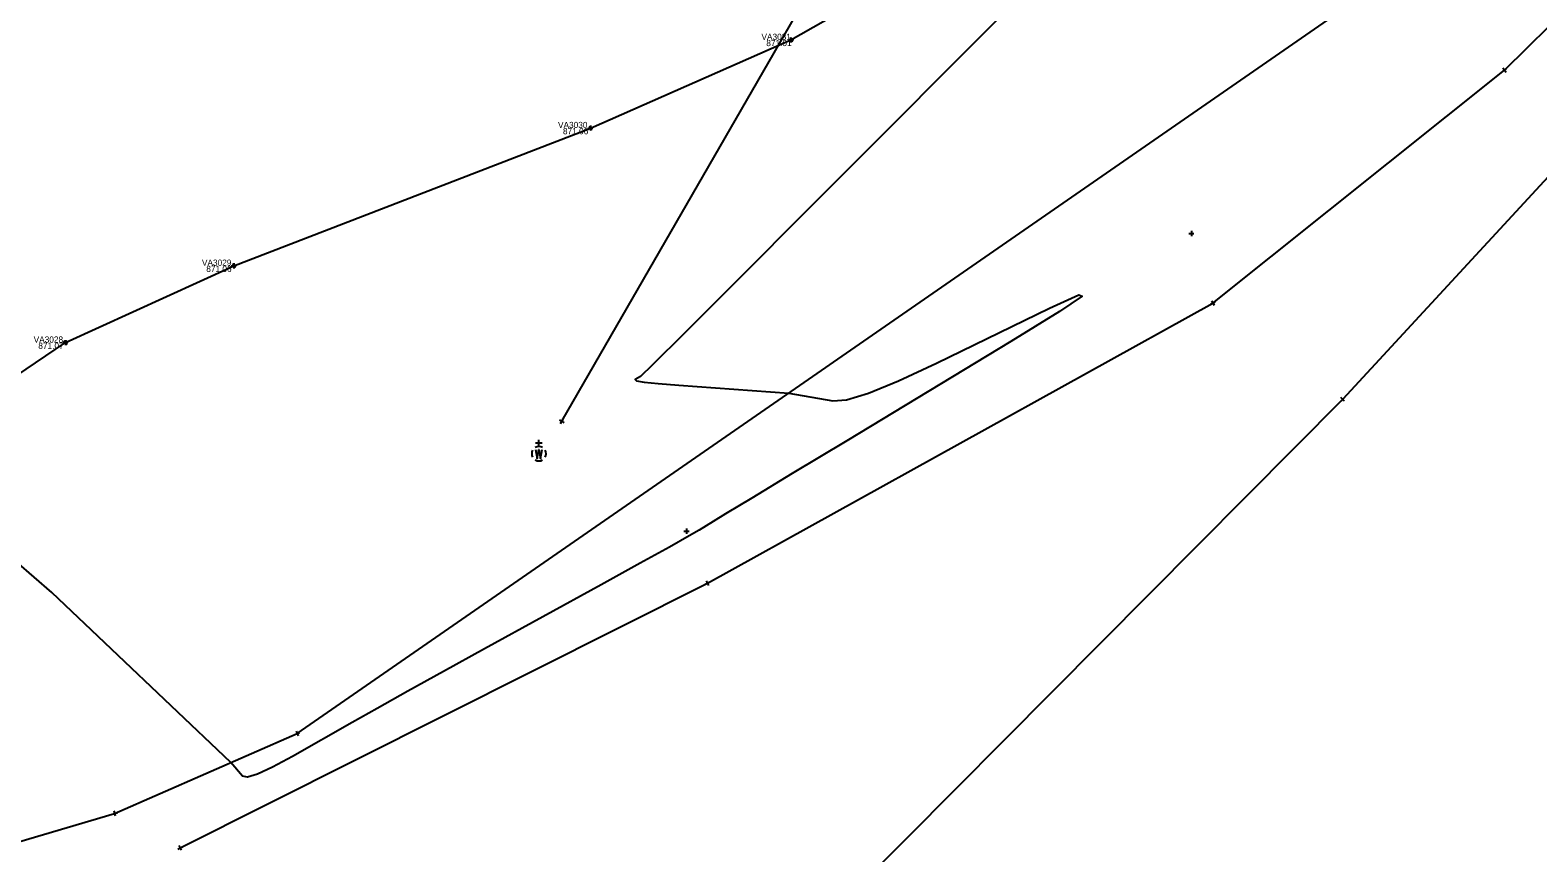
# Model space of a CAD drawing. Extents: x 1475580 to 1482245, y 377938 to 382467.
# Drawn here: x 1481280.89 to 1481295.51, y 378080.79 to 378088.76 of the extents above; entities that cross this region are included whole.
import ezdxf

# ---------------------------------------------------------------- set-up
doc = ezdxf.new("R2010")
doc.units = 0
for name, color, linetype in [('DT_X_Contour_Minor', 7, 'Continuous'), ('PV_X_Curb', 7, 'Continuous'), ('PV_X_EOP', 7, 'Continuous'), ('PV_X_Walk', 7, 'Continuous'), ('SV_X_Shot_Marker', 7, 'Continuous'), ('SV_X_Text_Elevation', 7, 'Continuous'), ('SV_X_Text_Name', 7, 'Continuous'), ('UT_X_Water', 7, 'Continuous'), ('UT_X_Water_Cells', 7, 'Continuous')]:
    doc.layers.add(name, color=color, linetype=linetype)

msp = doc.modelspace()

# ---------------------------------------------------------------- linework, layer by layer
at = {"layer": 'DT_X_Contour_Minor'}
msp.add_lwpolyline([(1481290.585, 378089.188), (1481288.447, 378087.042), (1481287.744, 378086.336), (1481287.236, 378085.829), (1481286.924, 378085.52), (1481286.808, 378085.409), (1481286.759, 378085.379), (1481286.771, 378085.368), (1481286.846, 378085.354), (1481286.982, 378085.34), (1481287.18, 378085.324), (1481288.248, 378085.248), (1481288.675, 378085.173), (1481288.807, 378085.184), (1481289.018, 378085.249), (1481289.309, 378085.367), (1481289.679, 378085.539), (1481290.773, 378086.07), (1481291.058, 378086.199), (1481291.09, 378086.189), (1481290.871, 378086.038), (1481290.4, 378085.748), (1481288.809, 378084.787), (1481288.281, 378084.468), (1481287.888, 378084.231), (1481287.633, 378084.077), (1481287.514, 378084.004), (1481287.378, 378083.921), (1481287.281, 378083.864), (1481287.09, 378083.757), (1481286.806, 378083.6), (1481286.429, 378083.392), (1481285.298, 378082.77), (1481284.899, 378082.551), (1481284.553, 378082.359), (1481284.258, 378082.194), (1481284.015, 378082.057), (1481283.437, 378081.728), (1481283.244, 378081.623), (1481283.099, 378081.557), (1481283.002, 378081.528), (1481282.953, 378081.537), (1481282.838, 378081.668), (1481281.105, 378083.318), (1481280.762, 378083.614)], dxfattribs=at)
msp.add_lwpolyline([(1481290.585, 378089.188), (1481288.447, 378087.042), (1481287.744, 378086.336), (1481287.236, 378085.829), (1481286.924, 378085.52), (1481286.808, 378085.409), (1481286.759, 378085.379), (1481286.771, 378085.368), (1481286.846, 378085.354), (1481286.982, 378085.34), (1481287.18, 378085.324), (1481288.248, 378085.248), (1481288.675, 378085.173), (1481288.807, 378085.184), (1481289.018, 378085.249), (1481289.309, 378085.367), (1481289.679, 378085.539), (1481290.773, 378086.07), (1481291.058, 378086.199), (1481291.09, 378086.189), (1481290.871, 378086.038), (1481290.4, 378085.748), (1481288.809, 378084.787), (1481288.281, 378084.468), (1481287.888, 378084.231), (1481287.633, 378084.077), (1481287.514, 378084.004), (1481287.378, 378083.921), (1481287.281, 378083.864), (1481287.09, 378083.757), (1481286.806, 378083.6), (1481286.429, 378083.392), (1481285.298, 378082.77), (1481284.899, 378082.551), (1481284.553, 378082.359), (1481284.258, 378082.194), (1481284.015, 378082.057), (1481283.437, 378081.728), (1481283.244, 378081.623), (1481283.099, 378081.557), (1481283.002, 378081.528), (1481282.953, 378081.537), (1481282.838, 378081.668), (1481281.105, 378083.318), (1481280.762, 378083.614)], dxfattribs=at)
at = {"layer": 'PV_X_Curb'}
for points in [[(1481260.817, 378083.891), (1481263.757, 378082.165), (1481266.786, 378080.843), (1481269.995, 378079.971), (1481273.12, 378079.589), (1481275.926, 378079.677), (1481277.731, 378080.003), (1481281.712, 378081.176), (1481283.483, 378081.95), (1481295.923, 378090.562), (1481299.451, 378094.31), (1481300.913, 378095.81), (1481302.083, 378097.025), (1481320.414, 378116.343), (1481340.859, 378137.833), (1481361.576, 378159.638), (1481382.233, 378181.406), (1481396.451, 378196.415), (1481396.638, 378196.668), (1481396.634, 378196.695)], [(1481282.347, 378080.842), (1481287.458, 378083.408), (1481292.356, 378086.121), (1481295.185, 378088.378), (1481296.787, 378089.957), (1481300.004, 378093.511), (1481302.707, 378096.342), (1481321.206, 378115.602), (1481341.53, 378137.195), (1481362.313, 378159.083), (1481382.833, 378180.775), (1481397.357, 378195.764)], [(1481282.347, 378080.842), (1481287.458, 378083.408), (1481292.356, 378086.121), (1481295.185, 378088.378), (1481296.787, 378089.957), (1481300.004, 378093.511), (1481302.707, 378096.342), (1481321.206, 378115.602), (1481341.53, 378137.195), (1481362.313, 378159.083), (1481382.833, 378180.775), (1481397.357, 378195.764)]]:
    msp.add_lwpolyline(points, dxfattribs=at)
at = {"layer": 'PV_X_EOP'}
msp.add_lwpolyline([(1481397.134, 378196.295), (1481398.125, 378195.357), (1481383.86, 378180.08), (1481363.147, 378158.397), (1481342.53, 378136.572), (1481321.954, 378114.976), (1481303.689, 378095.764), (1481300.826, 378092.849), (1481297.416, 378089.306), (1481293.616, 378085.188), (1481285.406, 378076.929), (1481276.1, 378066.71)], dxfattribs=at)
at = {"layer": 'PV_X_Walk'}
msp.add_lwpolyline([(1481277.844, 378081.512), (1481278.102, 378082.523), (1481278.872, 378083.779), (1481279.96, 378084.874), (1481281.235, 378085.737), (1481282.867, 378086.482), (1481286.324, 378087.816), (1481288.268, 378088.67), (1481289.952, 378089.633), (1481291.473, 378090.841), (1481292.695, 378092.342), (1481294.011, 378094.838), (1481295.108, 378097.02), (1481296.371, 378099.411), (1481297.678, 378101.265), (1481316.103, 378120.507), (1481336.541, 378141.928), (1481357.274, 378163.762), (1481377.97, 378185.403), (1481390.463, 378198.885)], dxfattribs=at)
at = {"layer": 'SV_X_Shot_Marker'}
for p, q in [((1481288.258, 378088.693), (1481288.278, 378088.647)), ((1481288.268, 378088.695), (1481288.268, 378088.645)), ((1481288.243, 378088.67), (1481288.293, 378088.67)), ((1481288.245, 378088.66), (1481288.291, 378088.68)), ((1481288.268, 378088.67), (1481288.268, 378088.67)), ((1481288.268, 378088.67), (1481288.268, 378088.67)), ((1481295.165, 378088.362), (1481295.204, 378088.394)), ((1481295.169, 378088.398), (1481295.2, 378088.358)), ((1481295.185, 378088.378), (1481295.185, 378088.378)), ((1481286.301, 378087.807), (1481286.347, 378087.825)), ((1481286.315, 378087.839), (1481286.333, 378087.793)), ((1481286.324, 378087.841), (1481286.324, 378087.791)), ((1481286.299, 378087.816), (1481286.349, 378087.816)), ((1481286.324, 378087.816), (1481286.324, 378087.816)), ((1481286.324, 378087.816), (1481286.324, 378087.816)), ((1481292.124, 378086.795), (1481292.174, 378086.795)), ((1481292.149, 378086.82), (1481292.149, 378086.77)), ((1481292.149, 378086.795), (1481292.149, 378086.795)), ((1481282.856, 378086.505), (1481282.877, 378086.459)), ((1481282.867, 378086.507), (1481282.867, 378086.457)), ((1481282.842, 378086.482), (1481282.892, 378086.482)), ((1481282.844, 378086.472), (1481282.889, 378086.492)), ((1481282.867, 378086.482), (1481282.867, 378086.482)), ((1481282.867, 378086.482), (1481282.867, 378086.482)), ((1481292.334, 378086.109), (1481292.378, 378086.133)), ((1481292.344, 378086.143), (1481292.368, 378086.099)), ((1481292.356, 378086.121), (1481292.356, 378086.121)), ((1481281.21, 378085.737), (1481281.26, 378085.737)), ((1481281.214, 378085.723), (1481281.256, 378085.751)), ((1481281.221, 378085.758), (1481281.249, 378085.717)), ((1481281.235, 378085.762), (1481281.235, 378085.712)), ((1481281.235, 378085.737), (1481281.235, 378085.737)), ((1481281.235, 378085.737), (1481281.235, 378085.737)), ((1481293.634, 378085.171), (1481293.598, 378085.205)), ((1481293.633, 378085.206), (1481293.599, 378085.169)), ((1481293.616, 378085.188), (1481293.616, 378085.188)), ((1481286.026, 378084.988), (1481286.07, 378084.963)), ((1481286.035, 378084.954), (1481286.06, 378084.997)), ((1481286.048, 378084.976), (1481286.048, 378084.976)), ((1481287.231, 378083.911), (1481287.281, 378083.911)), ((1481287.256, 378083.936), (1481287.256, 378083.886)), ((1481287.256, 378083.911), (1481287.256, 378083.911)), ((1481287.436, 378083.396), (1481287.481, 378083.419)), ((1481287.447, 378083.43), (1481287.47, 378083.385)), ((1481287.458, 378083.408), (1481287.458, 378083.408)), ((1481283.473, 378081.972), (1481283.493, 378081.927)), ((1481283.46, 378081.94), (1481283.506, 378081.96)), ((1481283.483, 378081.95), (1481283.483, 378081.95)), ((1481281.688, 378081.169), (1481281.736, 378081.183)), ((1481281.705, 378081.2), (1481281.719, 378081.152)), ((1481281.712, 378081.176), (1481281.712, 378081.176)), ((1481282.325, 378080.831), (1481282.37, 378080.853)), ((1481282.336, 378080.864), (1481282.359, 378080.82)), ((1481282.347, 378080.842), (1481282.347, 378080.842))]:
    msp.add_line(p, q, dxfattribs=at)
at = {"layer": 'UT_X_Water'}
msp.add_lwpolyline([(1481286.048, 378084.976), (1481288.471, 378089.181), (1481289.573, 378090.662), (1481299.67, 378098.828), (1481339.04, 378140.467), (1481368.748, 378172.374), (1481402.596, 378208.778), (1481408.786, 378214.206), (1481422.732, 378228.535), (1481423.857, 378229.722)], dxfattribs=at)
msp.add_lwpolyline([(1481286.048, 378084.976), (1481288.471, 378089.181), (1481289.573, 378090.662), (1481299.67, 378098.828), (1481339.04, 378140.467), (1481368.748, 378172.374), (1481402.596, 378208.778), (1481408.786, 378214.206), (1481422.732, 378228.535), (1481423.857, 378229.722)], dxfattribs=at)
at = {"layer": 'UT_X_Water_Cells'}
for p, q in [((1481285.856, 378084.763), (1481285.793, 378084.763)), ((1481285.825, 378084.731), (1481285.825, 378084.794)), ((1481285.825, 378084.661), (1481285.825, 378084.661))]:
    msp.add_line(p, q, dxfattribs=at)
msp.add_lwpolyline([(1481285.793, 378084.702), (1481285.809, 378084.616), (1481285.825, 378084.702), (1481285.841, 378084.616), (1481285.857, 378084.702)], dxfattribs=at)
for start, end in [(150.0184, 209.9816), (60.0184, 120.0157), (330.0184, 29.9816), (239.9843, 299.9816)]:
    msp.add_arc((1481285.825, 378084.661), 0.07, start, end, dxfattribs=at)

# ---------------------------------------------------------------- texts
at = {"layer": 'SV_X_Text_Elevation'}
for s, p in [('871.01', (1481288.029, 378088.61)), ('871.06', (1481286.058, 378087.756)), ('871.06', (1481282.601, 378086.422)), ('871.07', (1481280.973, 378085.677))]:
    msp.add_text(s, height=0.06, dxfattribs=at).set_placement(p)
at = {"layer": 'SV_X_Text_Name'}
for s, p in [('VA3031', (1481287.982, 378088.67)), ('VA3030', (1481286.01, 378087.816)), ('VA3029', (1481282.559, 378086.482)), ('VA3028', (1481280.928, 378085.737))]:
    msp.add_text(s, height=0.06, dxfattribs=at).set_placement(p)

doc.saveas('drawing.dxf')
